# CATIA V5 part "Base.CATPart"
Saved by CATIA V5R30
Part number: Base
Bounding box of the stored display mesh (mm): x -32 to 32, y 0 to 144, z 0 to 52
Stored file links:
  D:\PROJECTS\CATIA V56R 2020\Resources\Parts File\c12_catia_v5_6r2020_prt\c12_catia_v5-6r2020 figr_12-19\Base.CATPart
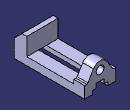
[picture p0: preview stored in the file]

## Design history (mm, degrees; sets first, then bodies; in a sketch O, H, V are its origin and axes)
Body1 (main body)
  Sketch1 on xy-plane, origin (0, 0, 0), H (1, 0, 0), V (0, 1, 0)
    point P1 (-32, 0)
    line L1 (-32, 0) -> (32, 0)
    line L2 (32, 0) -> (32, 144)
    line L3 (32, 144) -> (-32, 144)
    line L4 (-32, 144) -> (-32, 0)
    length L1 = 64
    length L2 = 144
    distance V L2 = 32
    coincidence: P1 H
    horizontal: L1 H, L3 H
    vertical: L2 V, L4 V
  Pad1: profile Sketch1, direction (0, 0, 1), length 16
  Sketch2 on face of Pad1, origin (32, 0, 0), H (0, 1, 0), V (0, 0, 1)
    point P1 (0, 16)
    line L1 (0, 16) -> (0, 36)
    point P2 (0, 36)
    line L2 (26, 52) -> (26, 16)
    line L3 (26, 16) -> (0, 16)
    reference projected line E1 (144, 16) -> (0, 16) from edge of Pad1
    line L4 (26, 52) -> (16, 52)
    point P5 (16, 52)
    line L5 (16, 52) -> (0, 36)
    length L2 = 36
    distance P5 P2 H = 16
    distance P5 P2 V = 16
    length L3 = 26
    coincidence: P1 V, E1 L3
    vertical: L1 V, L2 V
    horizontal: L3 H, L4 H
  Pad2: profile Sketch2, direction (-1, 0, 0), length 64
  Sketch3 on face of Pad1, origin (0, 144, 0), H (-1, 0, 0), V (0, 0, 1)
    line L1 (-32, 16) -> (-32, 24)
    point P2 (32, 24)
    line L2 (32, 24) -> (32, 16)
    line L3 (32, 16) -> (-32, 16)
    reference projected line E1 (32, 16) -> (-32, 16) from edge of Pad1
    line L4 (32, 24) -> (26, 24)
    point P4 (26, 24)
    line L5 (26, 24) -> (13.6777, 44.3018)
    point P5 (0, 52)
    line L6 (-13.6777, 44.3018) -> (-26, 24)
    point P6 (-26, 24)
    line L7 (-26, 24) -> (-32, 24)
    reference projected line E2 (32, 52) -> (-32, 52) from edge of Pad2
    reference projected line E3 (32, 16) -> (32, 52) from edge of Pad2
    reference projected line E4 (-32, 0) -> (-32, 16) from edge of Pad1
    arc A1 centre (0, 36) radius 16 from (13.6777, 44.3018) to (-13.6777, 44.3018) ccw
    point P8 (0, 36)
    reference projected line E5 (32, 52) -> (-32, 52) from edge of Pad2
    circle A2 centre (0, 36) radius 8
    distance H P2 = 24
    distance P6 P4 = 52
    distance P6 V = 26
    radius A1 = 16
    radius A2 = 8
    vertical: L1 V, L2 V
    horizontal: L3 H, L4 H, L7 H
    coincidence: L3 E1, P5 V, P6 L4, P5 E2, L2 E3, L1 E4, P8 V
    tangency: A1 E5, L6 A1, A1 L5
  Pad3: profile Sketch3, direction (0, -1, 0), length 22
  Fillet1: radius 3, on 2 edges
  Sketch4 on face of Pad1, origin (0, 144, 0), H (-1, 0, 0), V (0, 0, 1)
    point P1 (-16, 0)
    line L1 (-16, 0) -> (-16, 7)
    point P2 (-16, 7)
    line L2 (-16, 7) -> (-8, 7)
    point P3 (-8, 7)
    line L3 (-8, 7) -> (-8, 16)
    point P4 (-8, 16)
    line L4 (-8, 16) -> (0, 16)
    point P5 (0, 16)
    point P6 (16, 7)
    point P7 (16, 0)
    line L5 (16, 0) -> (16, 7)
    point P8 (8, 7)
    line L6 (16, 7) -> (8, 7)
    point P9 (8, 16)
    line L7 (8, 7) -> (8, 16)
    point P10 (0, 16)
    line L8 (8, 16) -> (0, 16)
    line L9 (-16, 0) -> (16, 0)
    point P11 (16, 0)
    distance L1 V = 16
    distance L3 V = 8
    distance H L4 = 16
    distance H L2 = 7
    coincidence: P1 H, P5 V, P7 P11, P5 P10
    vertical: L1 V, L3 V
    horizontal: L2 H, L4 H, L9 H
    symmetry: P2 P6 V, P1 P7 V, L1 L5 V, P3 P8 V, L2 L6 V, P4 P9 V, L3 L7 V, P5 P10 V, L4 L8 V
  Pocket1: profile Sketch4, direction (0, -1, 0), through (limit type 3)
  Sketch5 on face of Pad1, origin (0, 0, 0), H (1, 0, 0), V (0, -1, 0)
    circle A1 centre (22, -38) radius 3
    point P1 (22, -38)
    reference projected line E1 (32, 0) -> (-32, 0) from edge of Pad1
    radius A1 = 3
    distance P1 E1 = 38
    distance V P1 = 22
  Pocket2: profile Sketch5, direction (0, 0, 1), length 12
  RectPattern1: of Pocket2, direction 1 instances 2, spacing 70, along edge of Pad1, direction 2 instances 2, spacing 44, along edge of Pad1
